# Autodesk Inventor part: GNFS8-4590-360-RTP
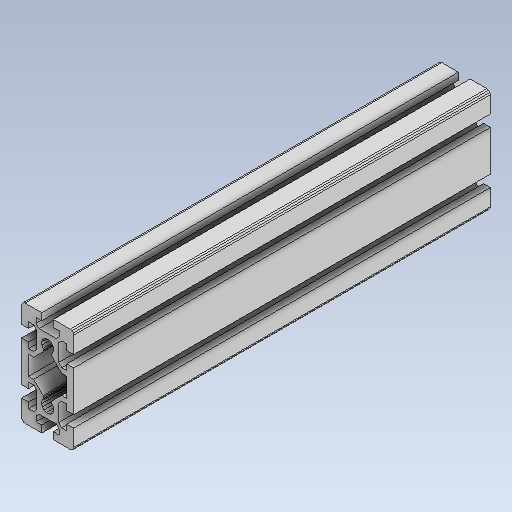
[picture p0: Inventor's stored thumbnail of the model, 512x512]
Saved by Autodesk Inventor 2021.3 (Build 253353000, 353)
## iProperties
Created: 2022-02
Part Number: GNFS8-4590-360-RTP
Material: 一般
Document SubType Name: Modeling
Designer: kengo
Density: 1 g/cm^3
Appearance: 既定
Author: kengo
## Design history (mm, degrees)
feature "GNFS8-4590-360-RTP"
node "ソリッド1"
